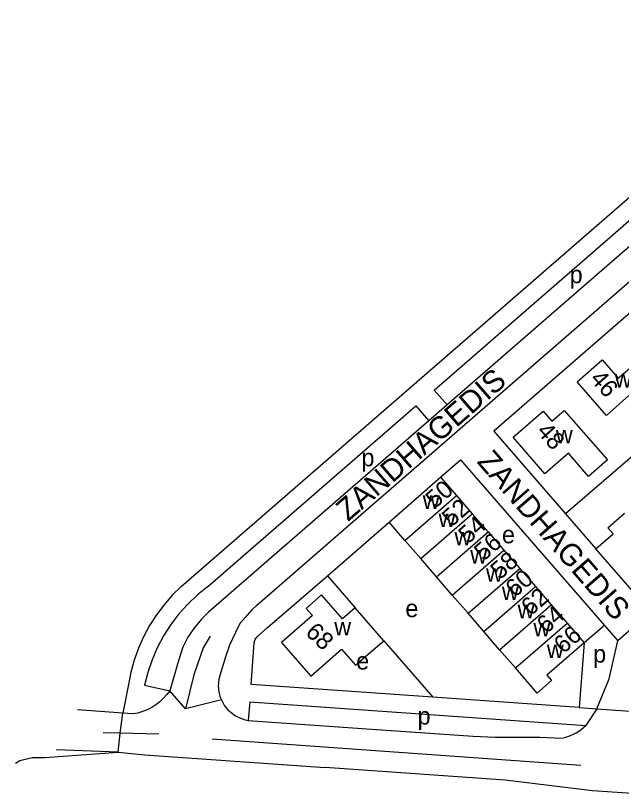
# Model space of a CAD drawing. Extents: x 155854 to 157362, y 383621 to 384685.
# Drawn here: x 155854.4 to 155992.5, y 383988.1 to 384165.7 of the extents above; entities that cross this region are included whole.
import ezdxf

# ---------------------------------------------------------------- set-up
doc = ezdxf.new("R2010")
doc.units = 0
for name, color, linetype in [('BLT_Basislijn', 7, 'Continuous'), ('BLT_Bebouwing', 7, 'Continuous'), ('BLT_Centroide', 7, 'Continuous'), ('BLT_Huisnummer', 7, 'Continuous'), ('BLT_Huisnummer_ tussenligend', 7, 'Continuous'), ('BLT_Onderverdeling_panden', 7, 'Continuous'), ('BLT_Straatnaam', 7, 'Continuous'), ('BLT_Vlakafsluiter', 7, 'Continuous')]:
    doc.layers.add(name, color=color, linetype=linetype)

msp = doc.modelspace()

# ---------------------------------------------------------------- linework, layer by layer
at = {"layer": 'BLT_Basislijn'}
for p, q in [((155892.15, 384035.54), (156042.02, 384165.73)), ((156043.1, 384155.4), (155952.77, 384076.94)), ((155909.37, 384031.28), (156026.31, 384132.88)), ((156070.03, 384130.46), (155979.82, 384052.08)), ((156111.16, 384127.33), (155991.68, 384023.17)), ((155949.82, 384080.34), (155952.77, 384076.94)), ((155945.69, 384076.74), (155948.64, 384073.34)), ((155952.77, 384076.94), (155948.64, 384073.34)), ((155948.64, 384073.34), (155898.42, 384029.72)), ((155951.31, 384060.46), (155955.87, 384064.4)), ((155979.82, 384052.08), (155986.7, 384044.17)), ((155925.49, 384038), (155939.54, 384050.22)), ((155925.49, 384038), (155931.8, 384030.69)), ((155988.66, 384026.65), (155991.68, 384023.17)), ((155938.33, 384023.19), (155949.55, 384010.31)), ((155989.71, 384014.48), (155991.68, 384023.17)), ((155986.95, 384007.69), (155989.71, 384014.48)), ((155880.13, 384013.2), (155878.84, 384006.67)), ((155883.79, 384013.07), (155889.57, 384011.79)), ((155907.77, 384009.23), (155907.42, 384005.03)), ((155907.77, 384009.23), (155984.41, 384003.85)), ((155982.93, 384007.96), (155986.95, 384007.69)), ((155878.84, 384006.67), (155868.52, 384007.45)), ((155986.95, 384007.69), (155984.41, 384003.85)), ((155907.42, 384005.03), (155933.39, 384003.17)), ((155933.39, 384003.17), (155958.73, 384001.39)), ((155878.28, 384002.09), (155874.37, 384002.18)), ((155887.03, 384001.88), (155878.28, 384002.09)), ((155899.21, 384000.81), (155983.28, 383994.81)), ((155958.73, 384001.39), (155963.72, 384001.17)), ((155963.72, 384001.17), (155968.73, 384001.19)), ((155968.73, 384001.19), (155973.92, 384001.21)), ((155973.92, 384001.21), (155978.95, 384000.97)), ((155877.76, 383997.74), (155863.63, 383998.34))]:
    msp.add_line(p, q, dxfattribs=at)
for points in [[(155949.82, 384080.34), (156040.15, 384158.81)], [(156053.63, 384149.33), (155963.42, 384070.96), (155979.82, 384052.08)], [(155898.19, 384035.48), (155945.69, 384076.74)], [(155955.87, 384064.4), (155988.66, 384026.65)], [(155949.55, 384010.31), (155908.09, 384013.22), (155908.82, 384022.71), (155909.04, 384023.54), (155909.55, 384024.16), (155911.86, 384026.17), (155925.49, 384038)], [(155892.15, 384035.54), (155890.13, 384033.55), (155888.25, 384031.4), (155886.52, 384029.09), (155884.96, 384026.65), (155883.58, 384024.1), (155882.4, 384021.45), (155881.43, 384018.74), (155880.67, 384015.98), (155880.13, 384013.2)], [(155898.19, 384035.48), (155895.87, 384033.61), (155893.68, 384031.54), (155891.65, 384029.28), (155889.8, 384026.85), (155888.15, 384024.28), (155886.71, 384021.59), (155885.51, 384018.8), (155884.53, 384015.95), (155883.79, 384013.07)], [(155909.37, 384031.28), (155908.28, 384030.19), (155906.74, 384028.48), (155905.55, 384027.11), (155904.52, 384025.06), (155903.15, 384022.16), (155902.3, 384019.76), (155900.95, 384015.23)], [(155898.42, 384029.72), (155896.76, 384028.11), (155895.01, 384025.94), (155893.67, 384023.98), (155892.53, 384021.71), (155891.5, 384018.4), (155889.57, 384011.79)], [(155988.66, 384026.65), (155984.07, 384022.69)], [(155898.74, 384024.21), (155897.18, 384021.6), (155895.01, 384015.41), (155893.11, 384007.67)], [(155984.07, 384022.69), (155982.93, 384007.96)], [(155900.95, 384015.23), (155900.73, 384014.39), (155900.64, 384013.53), (155900.61, 384012.91), (155900.64, 384012.23), (155900.73, 384011.47), (155900.98, 384010.57), (155901.32, 384009.69)], [(155889.57, 384011.79), (155888.9, 384010.9), (155888.15, 384010.05), (155887.32, 384009.27), (155886.41, 384008.57), (155885.43, 384007.95), (155884.41, 384007.43), (155883.34, 384007.01), (155882.26, 384006.7), (155881.16, 384006.48), (155878.84, 384006.67)], [(155901.32, 384009.69), (155902.02, 384008.36), (155902.82, 384007.41), (155903.53, 384006.79), (155904.54, 384006.02), (155905.49, 384005.59), (155906.73, 384005.16), (155907.42, 384005.03)], [(155982.93, 384007.96), (155949.55, 384010.31)], [(155978.95, 384000.97), (155979.62, 384001.13), (155980.28, 384001.33), (155980.94, 384001.57), (155981.57, 384001.86), (155982.19, 384002.19), (155982.79, 384002.55), (155983.36, 384002.95), (155983.9, 384003.39), (155984.41, 384003.85)], [(155854.4, 383995.3), (155855.37, 383995.85), (155858.2, 383996.52), (155861.04, 383996.52), (155877.76, 383997.74)], [(155877.76, 383997.74), (155883.87, 383997.13), (155924.95, 383994.24)], [(155999.85, 383988.14), (155993.83, 383988.4), (155985.97, 383988.95), (155966.02, 383991.36), (155924.95, 383994.24)]]:
    msp.add_lwpolyline(points, dxfattribs=at)
at = {"layer": 'BLT_Bebouwing'}
for p, q in [((155982.43, 384082.21), (155988.18, 384087.23)), ((155988.18, 384087.23), (155991.81, 384083.08)), ((155991.81, 384083.08), (155994.51, 384085.43)), ((155989.1, 384074.57), (155982.43, 384082.21)), ((155994.26, 384079.09), (155989.1, 384074.57)), ((155967.87, 384069.58), (155974.68, 384075.49)), ((155974.68, 384075.49), (155976.64, 384073.22)), ((155976.64, 384073.22), (155979.51, 384075.71)), ((155979.51, 384075.71), (155989.36, 384064.4)), ((155975.09, 384061.27), (155967.87, 384069.58)), ((155980.45, 384065.94), (155975.09, 384061.27)), ((155985.06, 384060.65), (155980.45, 384065.94)), ((155989.36, 384064.4), (155985.06, 384060.65)), ((155939.54, 384050.22), (155951.31, 384060.46)), ((155951.31, 384060.46), (155954.93, 384056.29)), ((155954.93, 384056.29), (155958.53, 384052.13)), ((155958.53, 384052.13), (155962.14, 384047.98)), ((155943.15, 384046.06), (155939.54, 384050.22)), ((155962.14, 384047.98), (155965.74, 384043.82)), ((155946.76, 384041.9), (155943.15, 384046.06)), ((155965.74, 384043.82), (155969.34, 384039.67)), ((155950.36, 384037.75), (155946.76, 384041.9)), ((155969.34, 384039.67), (155972.95, 384035.51)), ((155953.96, 384033.59), (155950.36, 384037.75)), ((155972.95, 384035.51), (155976.55, 384031.36)), ((155924.18, 384033.62), (155920.65, 384030.55)), ((155928.9, 384028.17), (155924.18, 384033.62)), ((155957.57, 384029.44), (155953.96, 384033.59)), ((155976.55, 384031.36), (155980.15, 384027.2)), ((155920.65, 384030.55), (155922.06, 384028.94)), ((155931.8, 384030.69), (155928.9, 384028.17)), ((155938.33, 384023.19), (155931.8, 384030.69)), ((155961.17, 384025.28), (155957.57, 384029.44)), ((155922.06, 384028.94), (155915, 384022.79)), ((155980.15, 384027.2), (155984.07, 384022.69)), ((155964.77, 384021.13), (155961.17, 384025.28)), ((155915, 384022.79), (155921.68, 384015.12)), ((155921.68, 384015.12), (155928.74, 384021.25)), ((155928.74, 384021.25), (155931.88, 384017.62)), ((155968.38, 384016.97), (155964.77, 384021.13)), ((155973.35, 384011.24), (155968.38, 384016.97))]:
    msp.add_line(p, q, dxfattribs=at)
for points in [[(155986.7, 384044.17), (155990.64, 384047.59), (155989.46, 384048.95), (155993.26, 384052.25)], [(156000.72, 384037.52), (155996.02, 384033.44), (155986.7, 384044.17)], [(155931.88, 384017.62), (155935.42, 384020.68), (155938.33, 384023.19)], [(155984.07, 384022.69), (155975.55, 384015.3), (155976.62, 384014.08), (155973.35, 384011.24)]]:
    msp.add_lwpolyline(points, dxfattribs=at)
at = {"layer": 'BLT_Onderverdeling_panden'}
for p, q in [((155943.15, 384046.06), (155954.93, 384056.29)), ((155946.76, 384041.9), (155958.53, 384052.13)), ((155950.36, 384037.75), (155962.14, 384047.98)), ((155953.96, 384033.59), (155965.74, 384043.82)), ((155957.57, 384029.44), (155969.34, 384039.67)), ((155961.17, 384025.28), (155972.95, 384035.51)), ((155964.77, 384021.13), (155976.55, 384031.36)), ((155968.38, 384016.97), (155980.15, 384027.2))]:
    msp.add_line(p, q, dxfattribs=at)
at = {"layer": 'BLT_Vlakafsluiter'}
for p, q in [((155893.11, 384007.67), (155889.57, 384011.79)), ((155901.32, 384009.69), (155893.11, 384007.67)), ((155878.28, 384002.09), (155878.84, 384006.67)), ((155986.95, 384007.69), (155996.9, 384006.98)), ((155877.76, 383997.74), (155878.28, 384002.09))]:
    msp.add_line(p, q, dxfattribs=at)

# ---------------------------------------------------------------- texts
at = {"layer": 'BLT_Centroide'}
for s, p in [('p', (155980.72, 384104.7)), ('w', (155991.02, 384080.91)), ('w', (155977.58, 384068.19)), ('p', (155933.25, 384062.96)), ('w', (155947.23, 384053.25)), ('w', (155950.84, 384049.09)), ('w', (155954.45, 384044.94)), ('e', (155965.29, 384045.4)), ('w', (155958.05, 384040.78)), ('w', (155961.65, 384036.62)), ('w', (155965.26, 384032.47)), ('e', (155943.26, 384028.56)), ('w', (155968.86, 384028.31)), ('w', (155927.05, 384024.38)), ('w', (155972.46, 384024.16)), ('w', (155975.52, 384019.22)), ('p', (155986.08, 384018.19)), ('e', (155932.05, 384016.61)), ('p', (155946.05, 384004.06))]:
    msp.add_text(s, height=4, dxfattribs=at).set_placement(p)
at = {"layer": 'BLT_Huisnummer'}
for s, rotation, p in [('46', 311.4651, (155985.17, 384082.77)), ('48', 311.4651, (155973, 384070.81)), ('50', 40.984, (155950.04, 384053.2)), ('54', 40.984, (155957.51, 384045.08)), ('58', 40.984, (155964.83, 384036.95)), ('62', 40.984, (155971.81, 384028.67)), ('68', 316.5084, (155920.25, 384024.82)), ('66', 40.984, (155979.29, 384020.05))]:
    msp.add_text(s, height=4, rotation=rotation, dxfattribs=at).set_placement(p)
at = {"layer": 'BLT_Huisnummer_ tussenligend'}
for s, p in [('52', (155953.78, 384048.98)), ('56', (155961.09, 384041.18)), ('60', (155968.24, 384032.89)), ('64', (155975.39, 384024.61))]:
    msp.add_text(s, height=4, rotation=40.984, dxfattribs=at).set_placement(p)
at = {"layer": 'BLT_Straatnaam'}
for rotation, p in [(40.9815, (155930.2, 384050.23)), (310.9815, (155959.41, 384063.91))]:
    msp.add_text('ZANDHAGEDIS', height=5, rotation=rotation, dxfattribs=at).set_placement(p)

doc.saveas('drawing.dxf')
